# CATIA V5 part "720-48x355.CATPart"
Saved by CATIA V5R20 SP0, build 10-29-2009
Part number: 720-48x355
Definition: NONE
Nomenclature: 720-48x355
Source: Unknown
Description: 720-48x355
Bounding box of the stored display mesh (mm): x 0 to 355, y -24 to 24, z -24 to 24
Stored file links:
  C:\Users\Utente\Desktop\IO LAVORO\3D X SITO CF\X SITO\720\720-48x355.CATPart
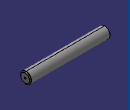
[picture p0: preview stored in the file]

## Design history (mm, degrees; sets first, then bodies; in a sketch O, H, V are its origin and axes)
Body1 "720-48x355" (main body)
  Solid1: solid without history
